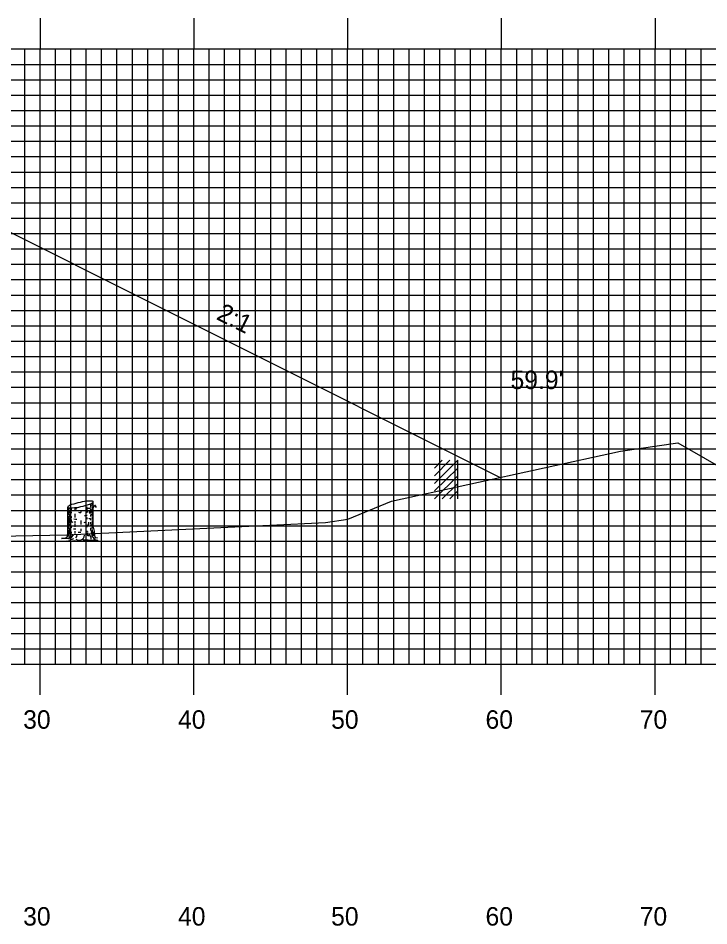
# Model space of a CAD drawing. Extents: x 1789730 to 1790074, y 442591 to 442811.
# Drawn here: x 1789924.8 to 1789969.7, y 442706.6 to 442765.7 of the extents above; entities that cross this region are included whole.
import ezdxf

# ---------------------------------------------------------------- set-up
doc = ezdxf.new("R2010")
doc.units = 0
for name, color, linetype in [('ANNOTATION', 7, 'Continuous'), ('D_Roadway_SlopeLines', 7, 'Continuous'), ('D_Text_Standard', 7, 'Continuous'), ('H_V ANNOTATION', 7, 'Continuous'), ('M_Buildings_Attachments', 7, 'Continuous'), ('M_Trees_Conifer_Pay', 7, 'Continuous'), ('MAJOR', 7, 'Continuous'), ('MINOR', 7, 'Continuous'), ('S_Roadway_Centerline', 7, 'Continuous')]:
    doc.layers.add(name, color=color, linetype=linetype)

msp = doc.modelspace()

# ---------------------------------------------------------------- linework, layer by layer
at = {"layer": 'D_Roadway_SlopeLines'}
msp.add_lwpolyline([(1789919.183, 442754.277), (1789956.118, 442735.81)], dxfattribs=at)
at = {"layer": 'M_Buildings_Attachments'}
for p, q in [((1789951.847, 442735.421), (1789953.356, 442736.93)), ((1789951.847, 442735.913), (1789952.831, 442736.93)), ((1789951.847, 442736.405), (1789952.339, 442736.93)), ((1789953.356, 442734.404), (1789953.356, 442736.93)), ((1789951.847, 442734.929), (1789953.356, 442736.405)), ((1789951.847, 442734.404), (1789953.356, 442735.913)), ((1789952.339, 442734.404), (1789953.356, 442735.421)), ((1789952.831, 442734.404), (1789953.356, 442734.929))]:
    msp.add_line(p, q, dxfattribs=at)
at = {"layer": 'M_Trees_Conifer_Pay'}
for p, q in [((1789929.455, 442734.081), (1789929.455, 442733.858)), ((1789929.573, 442734.142), (1789929.573, 442733.979)), ((1789929.573, 442733.912), (1789929.573, 442733.784)), ((1789929.644, 442732.567), (1789929.644, 442734.214)), ((1789927.98, 442732.157), (1789927.98, 442733.879)), ((1789928.028, 442733.841), (1789928.028, 442733.37)), ((1789928.028, 442733.306), (1789928.028, 442732.997)), ((1789928.086, 442733.83), (1789928.086, 442733.732)), ((1789928.086, 442733.658), (1789928.086, 442733.454)), ((1789928.086, 442733.396), (1789928.086, 442733.197)), ((1789928.211, 442733.822), (1789928.211, 442733.59)), ((1789928.211, 442733.549), (1789928.211, 442733.475)), ((1789928.431, 442733.843), (1789928.431, 442733.675)), ((1789928.431, 442733.438), (1789928.431, 442733.201)), ((1789928.837, 442733.611), (1789928.837, 442733.516)), ((1789929.227, 442733.885), (1789929.227, 442733.685)), ((1789929.227, 442733.627), (1789929.227, 442733.539)), ((1789929.455, 442733.769), (1789929.455, 442733.722)), ((1789929.455, 442733.387), (1789929.455, 442733.255)), ((1789929.513, 442733.586), (1789929.461, 442733.526)), ((1789929.573, 442733.597), (1789929.573, 442733.261)), ((1789928.028, 442732.95), (1789928.028, 442732.458)), ((1789928.086, 442733.15), (1789928.086, 442732.814)), ((1789928.086, 442732.761), (1789928.086, 442732.625)), ((1789928.211, 442733.072), (1789928.211, 442732.933)), ((1789928.431, 442732.956), (1789928.431, 442732.804)), ((1789928.431, 442732.761), (1789928.431, 442732.587)), ((1789928.837, 442732.997), (1789928.837, 442732.923)), ((1789928.837, 442732.898), (1789928.837, 442732.75)), ((1789929.227, 442733.191), (1789929.227, 442733.086)), ((1789929.227, 442732.719), (1789929.227, 442732.573)), ((1789929.455, 442733.144), (1789929.455, 442733.034)), ((1789929.455, 442732.898), (1789929.455, 442732.757)), ((1789929.573, 442733.224), (1789929.573, 442733.061)), ((1789929.573, 442733.014), (1789929.573, 442732.797)), ((1789929.573, 442732.767), (1789929.573, 442732.692)), ((1789928.028, 442732.404), (1789928.028, 442732.157)), ((1789928.086, 442732.526), (1789928.086, 442732.147)), ((1789928.211, 442732.662), (1789928.211, 442732.52)), ((1789928.211, 442732.258), (1789928.211, 442732.164)), ((1789928.431, 442732.31), (1789928.431, 442732.157)), ((1789928.837, 442732.458), (1789928.837, 442732.305)), ((1789929.227, 442732.341), (1789929.227, 442732.252)), ((1789929.455, 442732.53), (1789929.455, 442732.357)), ((1789929.573, 442732.652), (1789929.573, 442732.478)), ((1789928.211, 442731.764), (1789928.374, 442731.828)), ((1789928.648, 442731.7), (1789928.522, 442731.764))]:
    msp.add_line(p, q, dxfattribs=at)
for points in [[(1789929.461, 442733.712), (1789929.498, 442733.638), (1789929.545, 442733.695), (1789929.603, 442733.763), (1789929.696, 442733.957), (1789929.76, 442734.004), (1789929.791, 442734.011)], [(1789929.476, 442733.459), (1789929.513, 442733.586), (1789929.576, 442733.702), (1789929.607, 442733.769), (1789929.676, 442733.915)], [(1789929.69, 442733.945), (1789929.766, 442733.953), (1789929.838, 442733.854)], [(1789929.428, 442733.675), (1789929.397, 442733.59), (1789929.393, 442733.522), (1789929.424, 442733.459)], [(1789928.16, 442733.184), (1789928.154, 442733.28), (1789928.197, 442733.257), (1789928.197, 442733.162)], [(1789929.299, 442732.786), (1789929.311, 442732.709), (1789929.358, 442732.719), (1789929.346, 442732.886)], [(1789929.644, 442732.567), (1789929.696, 442732.305), (1789929.712, 442732.032), (1789929.77, 442731.906), (1789929.906, 442731.875), (1789929.675, 442731.838), (1789929.675, 442731.838), (1789929.681, 442731.791), (1789929.929, 442731.696), (1789929.654, 442731.713), (1789929.299, 442731.733), (1789928.977, 442731.723), (1789928.984, 442731.805), (1789928.835, 442731.723), (1789928.648, 442731.7), (1789928.673, 442731.632), (1789928.405, 442731.675), (1789928.184, 442731.648), (1789927.892, 442731.665), (1789928.181, 442731.723), (1789928.211, 442731.764), (1789928.049, 442731.822), (1789927.812, 442731.832), (1789927.571, 442731.832), (1789927.913, 442731.89), (1789927.954, 442731.97), (1789927.98, 442732.157)], [(1789929.234, 442732.174), (1789929.245, 442732.048), (1789929.319, 442732.005)], [(1789929.471, 442732.279), (1789929.545, 442732.174), (1789929.55, 442732.001), (1789929.675, 442731.838)], [(1789929.57, 442732.425), (1789929.576, 442732.279), (1789929.623, 442732.211), (1789929.634, 442732.011)], [(1789928.028, 442732.11), (1789928.007, 442732.032), (1789927.987, 442731.937)], [(1789928.106, 442732.089), (1789928.112, 442731.974), (1789928.059, 442731.885), (1789928.049, 442731.822)], [(1789928.269, 442732.116), (1789928.269, 442731.984), (1789928.181, 442731.885)], [(1789928.495, 442731.875), (1789928.563, 442731.97), (1789928.59, 442732.11)], [(1789928.984, 442731.805), (1789929.058, 442731.947), (1789929.068, 442732.048)], [(1789929.513, 442731.785), (1789929.498, 442731.923), (1789929.424, 442732.052)]]:
    msp.add_lwpolyline(points, dxfattribs=at)
for centre, radius, start, end in [((1789928.012, 442733.877), 0.0314, 156.51582, 169.2194), ((1789928.031, 442733.869), 0.0527, 146.7194, 156.51582), ((1789928.056, 442733.853), 0.0817, 132.38868, 146.7194), ((1789928.169, 442733.728), 0.251, 124.2194, 132.38868), ((1789928.479, 442733.273), 0.802, 108.05939, 124.2194), ((1789929.836, 442729.111), 5.179, 101.7194, 108.05939), ((1789927.789, 442738.981), 5.179, 275.37941, 281.7194), ((1789929.836, 442729.111), 5.179, 95.37941, 101.7194), ((1789927.789, 442738.981), 5.179, 281.7194, 288.05939), ((1789929.426, 442733.469), 0.802, 79.2194, 95.37941), ((1789929.146, 442734.82), 0.802, 288.05939, 304.2194), ((1789929.313, 442734.528), 0.571, 284.43166, 292.41325), ((1789929.529, 442734.01), 0.251, 71.05013, 79.2194), ((1789929.456, 442734.364), 0.251, 304.2194, 312.38868), ((1789929.513, 442734.182), 0.172, 300, 311.25059), ((1789929.513, 442734.028), 0.172, 300, 311.25059), ((1789929.584, 442734.17), 0.0817, 56.7194, 71.05013), ((1789929.569, 442734.24), 0.0817, 312.38868, 326.7194), ((1789929.585, 442734.1), 0.0624, 311.25059, 330), ((1789929.585, 442733.945), 0.0624, 311.25059, 330), ((1789929.6, 442734.194), 0.0527, 46.92298, 56.7194), ((1789929.614, 442734.21), 0.0314, 34.2194, 46.92298), ((1789929.594, 442734.224), 0.0527, 326.7194, 336.51582), ((1789929.601, 442734.091), 0.0441, 330, 343.94846), ((1789929.601, 442733.936), 0.0441, 330, 343.94846), ((1789929.618, 442734.213), 0.0264, 23.40735, 34.2194), ((1789929.613, 442734.215), 0.0314, 336.51582, 349.2194), ((1789929.622, 442734.214), 0.0226, 11.7194, 23.40735), ((1789929.611, 442734.088), 0.0334, 343.94846, 354.21506), ((1789929.611, 442733.933), 0.0334, 343.94846, 354.21506), ((1789929.622, 442734.214), 0.0226, 0.03145, 11.7194), ((1789929.618, 442734.214), 0.0264, 349.2194, 0.03145), ((1789928.013, 442733.7), 0.0334, 163.94846, 180), ((1789928.013, 442733.7), 0.0334, 180, 196.05154), ((1789928.007, 442733.878), 0.0264, 169.2194, 180.03145), ((1789928.003, 442733.878), 0.0226, 180.03145, 191.7194), ((1789928.023, 442733.703), 0.0441, 196.05154, 210), ((1789928.003, 442733.878), 0.0226, 191.7194, 203.40735), ((1789928.007, 442733.88), 0.0264, 203.40735, 214.2194), ((1789928.011, 442733.883), 0.0314, 214.2194, 226.92298), ((1789928.039, 442733.713), 0.0624, 210, 228.74941), ((1789928.025, 442733.898), 0.0527, 226.92298, 236.7194), ((1789928.041, 442733.923), 0.0817, 236.7194, 251.05013), ((1789928.111, 442733.795), 0.172, 228.74941, 240), ((1789928.096, 442734.082), 0.251, 251.05013, 259.2194), ((1789928.31, 442734.14), 0.571, 240, 240.33672), ((1789928.312, 442733.929), 0.571, 240, 247.05866), ((1789928.199, 442734.624), 0.802, 259.2194, 275.37941), ((1789928.31, 442734.14), 0.571, 246.85973, 257.98457), ((1789928.813, 442737.891), 4.124, 264.6955, 266.73309), ((1789928.811, 442737.658), 4.124, 268.07512, 270), ((1789928.811, 442737.658), 4.124, 270, 270.35814), ((1789928.812, 442737.447), 4.124, 273.70524, 275.95043), ((1789928.811, 442737.658), 4.124, 275.78493, 277.05584), ((1789928.813, 442737.891), 4.124, 276.23804, 278.1032), ((1789929.313, 442734.373), 0.571, 278.1032, 284.36665), ((1789929.313, 442733.929), 0.571, 284.44928, 297.04285), ((1789929.313, 442734.373), 0.571, 297.0237, 300), ((1789929.611, 442733.489), 0.0334, 343.94846, 354.21506), ((1789928.013, 442733.254), 0.0334, 163.94846, 180), ((1789928.013, 442733.254), 0.0334, 180, 196.05154), ((1789928.013, 442733.044), 0.0334, 163.94846, 180), ((1789928.013, 442733.044), 0.0334, 180, 196.05154), ((1789928.013, 442732.807), 0.0334, 163.94846, 180), ((1789928.013, 442732.807), 0.0334, 180, 196.05154), ((1789928.023, 442733.257), 0.0441, 196.05154, 210), ((1789928.023, 442733.047), 0.0441, 196.05154, 210), ((1789928.023, 442732.81), 0.0441, 196.05154, 210), ((1789928.039, 442733.266), 0.0624, 210, 228.74941), ((1789928.039, 442733.056), 0.0624, 210, 228.74941), ((1789928.039, 442732.819), 0.0624, 210, 228.74941), ((1789928.111, 442733.348), 0.172, 228.74941, 240), ((1789928.111, 442733.138), 0.172, 228.74941, 240), ((1789928.111, 442732.902), 0.172, 228.74941, 240), ((1789928.31, 442733.693), 0.571, 240, 240.33672), ((1789928.31, 442733.483), 0.571, 240, 246.85973), ((1789928.31, 442733.247), 0.571, 240, 246.85973), ((1789928.31, 442733.483), 0.571, 259.27072, 261.8968), ((1789928.811, 442737.001), 4.124, 261.8968, 263.14738), ((1789928.811, 442737.211), 4.124, 264.08098, 266.66759), ((1789928.811, 442737.001), 4.124, 270, 270.35814), ((1789928.811, 442737.001), 4.124, 273.14934, 275.45691), ((1789928.811, 442737.211), 4.124, 277.61247, 278.1032), ((1789929.312, 442733.693), 0.571, 278.1032, 286.92962), ((1789929.312, 442733.247), 0.571, 285.39827, 297.18959), ((1789929.312, 442733.693), 0.571, 297.18959, 300), ((1789929.312, 442733.483), 0.571, 297.18959, 300), ((1789929.511, 442733.348), 0.172, 300, 311.25059), ((1789929.511, 442733.138), 0.172, 300, 311.25059), ((1789929.584, 442733.266), 0.0624, 311.25059, 330), ((1789929.584, 442733.056), 0.0624, 311.25059, 330), ((1789929.599, 442733.257), 0.0441, 330, 343.94846), ((1789929.599, 442733.047), 0.0441, 330, 343.94846), ((1789929.61, 442733.254), 0.0334, 343.94846, 354.21506), ((1789929.61, 442733.044), 0.0334, 343.94846, 354.21506), ((1789928.013, 442732.609), 0.0334, 163.94846, 180), ((1789928.013, 442732.414), 0.0334, 163.94846, 180), ((1789928.013, 442732.414), 0.0334, 180, 196.05154), ((1789928.013, 442732.193), 0.0334, 163.94846, 180), ((1789928.013, 442732.193), 0.0334, 180, 196.05154), ((1789928.023, 442732.417), 0.0441, 196.05154, 210), ((1789928.023, 442732.196), 0.0441, 196.05154, 210), ((1789928.039, 442732.426), 0.0624, 210, 228.74941), ((1789928.039, 442732.205), 0.0624, 210, 228.74941), ((1789928.111, 442732.508), 0.172, 228.74941, 240), ((1789928.111, 442732.288), 0.172, 228.74941, 240), ((1789928.3, 442733.055), 0.571, 241.23686, 248.02677), ((1789928.31, 442732.853), 0.571, 240, 246.85973), ((1789928.31, 442732.633), 0.571, 240, 244.53138), ((1789928.811, 442736.567), 4.124, 263.49906, 265.83975), ((1789928.811, 442736.764), 4.124, 264.71603, 266.31934), ((1789928.811, 442736.371), 4.124, 267.81166, 270), ((1789928.811, 442736.371), 4.124, 270, 270.13279), ((1789928.811, 442736.371), 4.124, 275.78493, 276.78961), ((1789929.312, 442732.853), 0.571, 288.50673, 297.27208), ((1789929.312, 442733.049), 0.571, 289.29072, 300), ((1789929.511, 442732.704), 0.172, 300, 311.25059), ((1789929.511, 442732.288), 0.172, 300, 311.25059), ((1789929.584, 442732.621), 0.0624, 311.25059, 330), ((1789929.584, 442732.205), 0.0624, 311.25059, 330), ((1789929.599, 442732.612), 0.0441, 330, 343.94846), ((1789929.599, 442732.196), 0.0441, 330, 343.94846), ((1789929.61, 442732.609), 0.0334, 343.94846, 354.21506), ((1789929.61, 442732.193), 0.0334, 343.94846, 354.21506), ((1789928.811, 442736.151), 4.124, 262.44379, 263.51202), ((1789928.811, 442736.151), 4.124, 277.36842, 278.1032), ((1789929.312, 442732.633), 0.571, 278.1032, 281.63703)]:
    msp.add_arc(centre, radius, start, end, dxfattribs=at)
at = {"layer": 'MAJOR'}
for p, q in [((1789926.183, 442765.669), (1789926.183, 442763.665)), ((1789936.183, 442765.669), (1789936.183, 442763.665)), ((1789946.183, 442765.669), (1789946.183, 442763.665)), ((1789956.183, 442765.669), (1789956.183, 442763.665)), ((1789966.183, 442765.669), (1789966.183, 442763.665)), ((1789756.183, 442763.665), (1790036.183, 442763.665)), ((1789756.183, 442763.665), (1790036.183, 442763.665)), ((1789926.183, 442723.665), (1789926.183, 442763.665)), ((1789936.183, 442723.665), (1789936.183, 442763.665)), ((1789946.183, 442723.665), (1789946.183, 442763.665)), ((1789956.183, 442723.665), (1789956.183, 442763.665)), ((1789966.183, 442723.665), (1789966.183, 442763.665)), ((1789756.183, 442758.665), (1790036.183, 442758.665)), ((1789756.183, 442753.665), (1790036.183, 442753.665)), ((1789756.183, 442748.665), (1790036.183, 442748.665)), ((1789756.183, 442743.665), (1790036.183, 442743.665)), ((1789756.183, 442738.665), (1790036.183, 442738.665)), ((1789756.183, 442733.665), (1790036.183, 442733.665)), ((1789756.183, 442728.665), (1790036.183, 442728.665)), ((1789756.183, 442723.665), (1790036.183, 442723.665)), ((1789756.183, 442723.665), (1790036.183, 442723.665)), ((1789926.183, 442721.661), (1789926.183, 442723.665)), ((1789936.183, 442721.661), (1789936.183, 442723.665)), ((1789946.183, 442721.661), (1789946.183, 442723.665)), ((1789956.183, 442721.661), (1789956.183, 442723.665)), ((1789966.183, 442721.661), (1789966.183, 442723.665))]:
    msp.add_line(p, q, dxfattribs=at)
at = {"layer": 'MINOR'}
for p, q in [((1789925.183, 442723.665), (1789925.183, 442763.665)), ((1789927.183, 442723.665), (1789927.183, 442763.665)), ((1789928.183, 442723.665), (1789928.183, 442763.665)), ((1789929.183, 442723.665), (1789929.183, 442763.665)), ((1789930.183, 442723.665), (1789930.183, 442763.665)), ((1789931.183, 442723.665), (1789931.183, 442763.665)), ((1789932.183, 442723.665), (1789932.183, 442763.665)), ((1789933.183, 442723.665), (1789933.183, 442763.665)), ((1789934.183, 442723.665), (1789934.183, 442763.665)), ((1789935.183, 442723.665), (1789935.183, 442763.665)), ((1789937.183, 442723.665), (1789937.183, 442763.665)), ((1789938.183, 442723.665), (1789938.183, 442763.665)), ((1789939.183, 442723.665), (1789939.183, 442763.665)), ((1789940.183, 442723.665), (1789940.183, 442763.665)), ((1789941.183, 442723.665), (1789941.183, 442763.665)), ((1789942.183, 442723.665), (1789942.183, 442763.665)), ((1789943.183, 442723.665), (1789943.183, 442763.665)), ((1789944.183, 442723.665), (1789944.183, 442763.665)), ((1789945.183, 442723.665), (1789945.183, 442763.665)), ((1789947.183, 442723.665), (1789947.183, 442763.665)), ((1789948.183, 442723.665), (1789948.183, 442763.665)), ((1789949.183, 442723.665), (1789949.183, 442763.665)), ((1789950.183, 442723.665), (1789950.183, 442763.665)), ((1789951.183, 442723.665), (1789951.183, 442763.665)), ((1789952.183, 442723.665), (1789952.183, 442763.665)), ((1789953.183, 442723.665), (1789953.183, 442763.665)), ((1789954.183, 442723.665), (1789954.183, 442763.665)), ((1789955.183, 442723.665), (1789955.183, 442763.665)), ((1789957.183, 442723.665), (1789957.183, 442763.665)), ((1789958.183, 442723.665), (1789958.183, 442763.665)), ((1789959.183, 442723.665), (1789959.183, 442763.665)), ((1789960.183, 442723.665), (1789960.183, 442763.665)), ((1789961.183, 442723.665), (1789961.183, 442763.665)), ((1789962.183, 442723.665), (1789962.183, 442763.665)), ((1789963.183, 442723.665), (1789963.183, 442763.665)), ((1789964.183, 442723.665), (1789964.183, 442763.665)), ((1789965.183, 442723.665), (1789965.183, 442763.665)), ((1789967.183, 442723.665), (1789967.183, 442763.665)), ((1789968.183, 442723.665), (1789968.183, 442763.665)), ((1789969.183, 442723.665), (1789969.183, 442763.665)), ((1789756.183, 442762.665), (1790036.183, 442762.665)), ((1789756.183, 442761.665), (1790036.183, 442761.665)), ((1789756.183, 442760.665), (1790036.183, 442760.665)), ((1789756.183, 442759.665), (1790036.183, 442759.665)), ((1789756.183, 442757.665), (1790036.183, 442757.665)), ((1789756.183, 442756.665), (1790036.183, 442756.665)), ((1789756.183, 442755.665), (1790036.183, 442755.665)), ((1789756.183, 442754.665), (1790036.183, 442754.665)), ((1789756.183, 442752.665), (1790036.183, 442752.665)), ((1789756.183, 442751.665), (1790036.183, 442751.665)), ((1789756.183, 442750.665), (1790036.183, 442750.665)), ((1789756.183, 442749.665), (1790036.183, 442749.665)), ((1789756.183, 442747.665), (1790036.183, 442747.665)), ((1789756.183, 442746.665), (1790036.183, 442746.665)), ((1789756.183, 442745.665), (1790036.183, 442745.665)), ((1789756.183, 442744.665), (1790036.183, 442744.665)), ((1789756.183, 442742.665), (1790036.183, 442742.665)), ((1789756.183, 442741.665), (1790036.183, 442741.665)), ((1789756.183, 442740.665), (1790036.183, 442740.665)), ((1789756.183, 442739.665), (1790036.183, 442739.665)), ((1789756.183, 442737.665), (1790036.183, 442737.665)), ((1789756.183, 442736.665), (1790036.183, 442736.665)), ((1789756.183, 442735.665), (1790036.183, 442735.665)), ((1789756.183, 442734.665), (1790036.183, 442734.665)), ((1789756.183, 442732.665), (1790036.183, 442732.665)), ((1789756.183, 442731.665), (1790036.183, 442731.665)), ((1789756.183, 442730.665), (1790036.183, 442730.665)), ((1789756.183, 442729.665), (1790036.183, 442729.665)), ((1789756.183, 442727.665), (1790036.183, 442727.665)), ((1789756.183, 442726.665), (1790036.183, 442726.665)), ((1789756.183, 442725.665), (1790036.183, 442725.665)), ((1789756.183, 442724.665), (1790036.183, 442724.665))]:
    msp.add_line(p, q, dxfattribs=at)
at = {"layer": 'S_Roadway_Centerline'}
msp.add_lwpolyline([(1789855.114, 442730.106), (1789871.397, 442730.329), (1789872.648, 442730.357), (1789884.881, 442730.97), (1789891.102, 442731.002), (1789905.186, 442731.549), (1789908.557, 442731.71), (1789912.403, 442731.759), (1789927.921, 442732.078), (1789941.118, 442732.699), (1789944.737, 442732.872), (1789946.197, 442733.083), (1789949.045, 442734.261), (1789963.934, 442737.521), (1789967.671, 442738.049), (1789971.222, 442736.013)], dxfattribs=at)

# ---------------------------------------------------------------- texts
at = {"layer": 'ANNOTATION'}
msp.add_text('2:1', height=1.2, rotation=333.43495, dxfattribs=at).set_placement((1789937.584, 442746.113))
at = {"layer": 'D_Text_Standard'}
msp.add_text("59.9'", height=1.2, dxfattribs=at).set_placement((1789956.784, 442741.551))
at = {"layer": 'H_V ANNOTATION'}
for s, p in [('30', (1789925.08, 442719.465)), ('40', (1789935.155, 442719.465)), ('50', (1789945.112, 442719.465)), ('60', (1789955.155, 442719.465)), ('70', (1789965.187, 442719.465)), ('30', (1789925.08, 442706.665)), ('40', (1789935.155, 442706.665)), ('50', (1789945.112, 442706.665)), ('60', (1789955.155, 442706.665)), ('70', (1789965.187, 442706.665))]:
    msp.add_text(s, height=1.2, dxfattribs=at).set_placement(p)

doc.saveas('drawing.dxf')
